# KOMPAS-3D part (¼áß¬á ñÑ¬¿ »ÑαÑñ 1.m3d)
File: created 06.04.2016 12:01:11, last saved 22.07.2016 16:02:09.
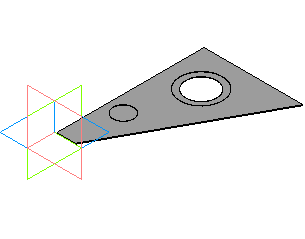
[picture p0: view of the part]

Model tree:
1. Эскиз:1
2. Операция выдавливания:1
     Толщина стенки 2 = 15; Расстояние 1 = 0.8; Расстояние 2 = 96.2519
3. Эскиз:2
4. Вырезать элемент выдавливания:1
     Толщина стенки 1 = 2; Толщина стенки 2 = 2; Расстояние 1 = 10
5. Эскиз:3
6. Вырезать элемент выдавливания:2
     Толщина стенки 1 = 2; Толщина стенки 2 = 2; Расстояние 1 = 10
7. Эскиз:4
8. Вырезать элемент выдавливания:3
     Толщина стенки 1 = 2; Толщина стенки 2 = 2; Расстояние 1 = 10
9. Эскиз:5
10. Вырезать элемент выдавливания:4
     Толщина стенки 1 = 2; Толщина стенки 2 = 2; Расстояние 1 = 0.4
11. Эскиз:6
12. Вырезать элемент выдавливания:5
     Толщина стенки 1 = 2; Толщина стенки 2 = 2; Расстояние 1 = 0.4
13. Эскиз:7
14. Вырезать элемент выдавливания:6
     Толщина стенки 1 = 2; Толщина стенки 2 = 2; Расстояние 1 = 10.4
